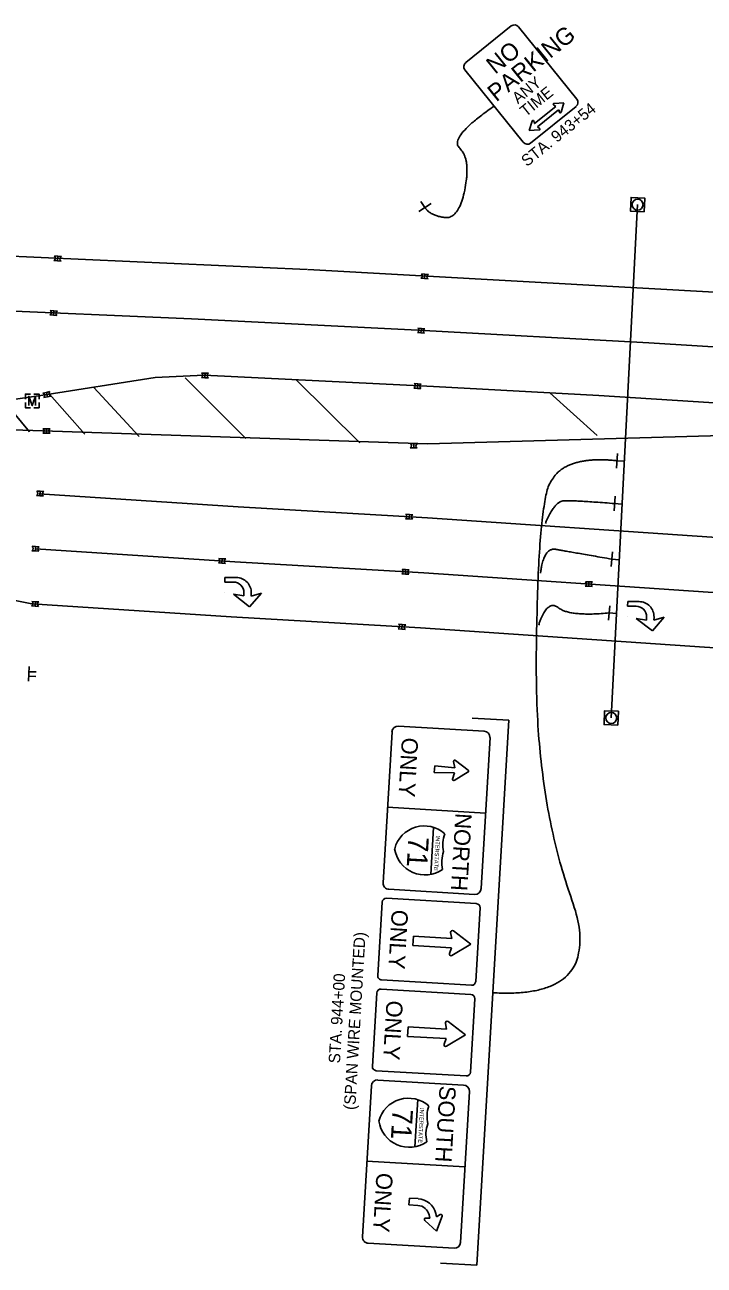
# Model space of a CAD drawing. Extents: x 1847379 to 1850904, y 217032 to 220169.
# Drawn here: x 1848407.3 to 1848555.2, y 218695.2 to 218965.5 of the extents above; entities that cross this region are included whole.
import ezdxf

# ---------------------------------------------------------------- set-up
doc = ezdxf.new("R2010")
doc.units = 0
for name, color, linetype in [('PM_P_Cells', 7, 'Continuous'), ('PM_P_Channelizing_Line', 7, 'Continuous'), ('PM_P_CL_Double_Solid', 7, 'Continuous'), ('PM_P_Edge_Line', 7, 'Continuous'), ('PM_P_Lane_Line', 7, 'Continuous'), ('PM_P_Transverse_Line', 7, 'Continuous'), ('SN_P_Signs', 7, 'Continuous'), ('SN_X_Foundation', 7, 'Continuous'), ('SN_X_Public', 7, 'Continuous'), ('SV_X_Mon_Cells_Found', 7, 'Continuous')]:
    doc.layers.add(name, color=color, linetype=linetype)

msp = doc.modelspace()

# ---------------------------------------------------------------- linework, layer by layer
at = {"layer": 'PM_P_Cells'}
for p, q in [((1848413.6, 218914.14), (1848414.37, 218914.07)), ((1848413.6, 218914.14), (1848414.37, 218914.07)), ((1848414.46, 218915.04), (1848413.69, 218915.11)), ((1848413.69, 218915.11), (1848414.46, 218915.04)), ((1848414.37, 218914.07), (1848414.46, 218915.04)), ((1848414.37, 218914.07), (1848415.14, 218914)), ((1848414.46, 218915.04), (1848415.23, 218914.97)), ((1848493.52, 218910.25), (1848494.28, 218910.18)), ((1848493.52, 218910.25), (1848494.28, 218910.18)), ((1848494.37, 218911.15), (1848493.6, 218911.22)), ((1848493.6, 218911.22), (1848494.37, 218911.15)), ((1848494.28, 218910.18), (1848494.37, 218911.15)), ((1848494.28, 218910.18), (1848495.05, 218910.11)), ((1848494.37, 218911.15), (1848495.14, 218911.08)), ((1848412.73, 218902.28), (1848413.49, 218902.21)), ((1848412.73, 218902.28), (1848413.49, 218902.21)), ((1848413.58, 218903.18), (1848412.81, 218903.25)), ((1848412.81, 218903.25), (1848413.58, 218903.18)), ((1848413.49, 218902.21), (1848413.58, 218903.18)), ((1848413.49, 218902.21), (1848414.26, 218902.14)), ((1848413.58, 218903.18), (1848414.35, 218903.11)), ((1848493.61, 218899.31), (1848492.84, 218899.38)), ((1848492.84, 218899.38), (1848493.61, 218899.31)), ((1848493.52, 218898.34), (1848493.61, 218899.31)), ((1848493.61, 218899.31), (1848494.37, 218899.24)), ((1848492.75, 218898.41), (1848493.52, 218898.34)), ((1848492.75, 218898.41), (1848493.52, 218898.34)), ((1848493.52, 218898.34), (1848494.29, 218898.27)), ((1848446.48, 218888.59), (1848445.71, 218888.6)), ((1848446.5, 218889.57), (1848445.72, 218889.58)), ((1848446.5, 218889.57), (1848446.48, 218888.59)), ((1848446.48, 218888.59), (1848447.25, 218888.58)), ((1848447.25, 218888.58), (1848446.48, 218888.59)), ((1848447.27, 218889.55), (1848446.5, 218889.57)), ((1848447.27, 218889.55), (1848446.5, 218889.57)), ((1848491.97, 218886.34), (1848492.73, 218886.27)), ((1848491.97, 218886.34), (1848492.73, 218886.27)), ((1848492.82, 218887.24), (1848492.05, 218887.31)), ((1848492.05, 218887.31), (1848492.82, 218887.24)), ((1848492.73, 218886.27), (1848492.82, 218887.24)), ((1848492.73, 218886.27), (1848493.5, 218886.2)), ((1848492.82, 218887.24), (1848493.59, 218887.17)), ((1848411.96, 218885.38), (1848411.21, 218885.21)), ((1848412.17, 218884.43), (1848411.42, 218884.26)), ((1848412.71, 218885.55), (1848411.96, 218885.38)), ((1848412.71, 218885.55), (1848411.96, 218885.38)), ((1848411.96, 218885.38), (1848412.17, 218884.43)), ((1848412.17, 218884.43), (1848412.93, 218884.6)), ((1848412.93, 218884.6), (1848412.17, 218884.43)), ((1848411.97, 218877.46), (1848411.2, 218877.46)), ((1848411.2, 218877.46), (1848411.97, 218877.46)), ((1848411.2, 218876.49), (1848411.97, 218876.49)), ((1848411.2, 218876.49), (1848411.97, 218876.49)), ((1848411.97, 218877.46), (1848412.75, 218877.46)), ((1848411.97, 218876.49), (1848411.97, 218877.46)), ((1848411.97, 218876.49), (1848412.75, 218876.49)), ((1848491.16, 218873.29), (1848491.93, 218873.29)), ((1848491.16, 218873.29), (1848491.93, 218873.29)), ((1848491.94, 218874.26), (1848491.17, 218874.27)), ((1848491.17, 218874.27), (1848491.94, 218874.26)), ((1848491.93, 218873.29), (1848491.94, 218874.26)), ((1848491.93, 218873.29), (1848492.7, 218873.28)), ((1848491.94, 218874.26), (1848492.71, 218874.26)), ((1848409.79, 218862.9), (1848410.56, 218862.86)), ((1848409.79, 218862.9), (1848410.56, 218862.86)), ((1848410.62, 218863.83), (1848409.85, 218863.88)), ((1848409.85, 218863.88), (1848410.62, 218863.83)), ((1848410.56, 218862.86), (1848410.62, 218863.83)), ((1848410.56, 218862.86), (1848411.33, 218862.82)), ((1848410.62, 218863.83), (1848411.39, 218863.79)), ((1848490.99, 218858.78), (1848490.22, 218858.84)), ((1848490.22, 218858.84), (1848490.99, 218858.78)), ((1848490.92, 218857.81), (1848490.99, 218858.78)), ((1848490.99, 218858.78), (1848491.76, 218858.73)), ((1848490.15, 218857.86), (1848490.92, 218857.81)), ((1848490.15, 218857.86), (1848490.92, 218857.81)), ((1848490.92, 218857.81), (1848491.69, 218857.75)), ((1848408.79, 218850.87), (1848409.55, 218850.83)), ((1848408.79, 218850.87), (1848409.55, 218850.83)), ((1848409.61, 218851.8), (1848408.84, 218851.85)), ((1848408.84, 218851.85), (1848409.61, 218851.8)), ((1848409.55, 218850.83), (1848409.61, 218851.8)), ((1848409.55, 218850.83), (1848410.32, 218850.79)), ((1848409.61, 218851.8), (1848410.38, 218851.76)), ((1848449.41, 218848.24), (1848450.18, 218848.18)), ((1848449.41, 218848.24), (1848450.18, 218848.18)), ((1848450.26, 218849.15), (1848449.49, 218849.21)), ((1848449.49, 218849.21), (1848450.26, 218849.15)), ((1848450.18, 218848.18), (1848450.26, 218849.15)), ((1848450.18, 218848.18), (1848450.95, 218848.12)), ((1848450.26, 218849.15), (1848451.03, 218849.09)), ((1848489.36, 218845.82), (1848490.13, 218845.8)), ((1848489.36, 218845.82), (1848490.13, 218845.8)), ((1848490.17, 218846.77), (1848489.4, 218846.8)), ((1848489.4, 218846.8), (1848490.17, 218846.77)), ((1848490.13, 218845.8), (1848490.17, 218846.77)), ((1848490.13, 218845.8), (1848490.9, 218845.77)), ((1848490.17, 218846.77), (1848490.94, 218846.74)), ((1848450.82, 218844.07), (1848450.83, 218845.07)), ((1848452.68, 218844.05), (1848450.82, 218844.07)), ((1848450.83, 218845.07), (1848453.31, 218845.05)), ((1848529.27, 218843.16), (1848530.04, 218843.13)), ((1848529.27, 218843.16), (1848530.04, 218843.13)), ((1848530.08, 218844.11), (1848529.31, 218844.14)), ((1848529.31, 218844.14), (1848530.08, 218844.11)), ((1848530.04, 218843.13), (1848530.08, 218844.11)), ((1848530.04, 218843.13), (1848530.81, 218843.1)), ((1848530.08, 218844.11), (1848530.85, 218844.08)), ((1848409.56, 218839.78), (1848408.8, 218839.84)), ((1848408.8, 218839.84), (1848409.56, 218839.78)), ((1848409.49, 218838.81), (1848409.56, 218839.78)), ((1848409.56, 218839.78), (1848410.33, 218839.73)), ((1848450.8, 218841.74), (1848450.8, 218841.74)), ((1848456.21, 218838.69), (1848452.72, 218841.39)), ((1848452.72, 218841.39), (1848454.95, 218841.03)), ((1848454.95, 218841.03), (1848454.96, 218841.73)), ((1848458.8, 218841.66), (1848456.21, 218838.69)), ((1848456.56, 218841.68), (1848456.55, 218841.02)), ((1848456.55, 218841.02), (1848458.8, 218841.66)), ((1848458.8, 218841.66), (1848458.8, 218841.66)), ((1848538.52, 218838.82), (1848538.53, 218839.82)), ((1848538.53, 218839.82), (1848541.01, 218839.8)), ((1848408.72, 218838.86), (1848409.49, 218838.81)), ((1848408.72, 218838.86), (1848409.49, 218838.81)), ((1848409.49, 218838.81), (1848410.26, 218838.75)), ((1848540.38, 218838.8), (1848538.52, 218838.82)), ((1848489.42, 218834.79), (1848488.65, 218834.87)), ((1848488.65, 218834.87), (1848489.42, 218834.79)), ((1848489.32, 218833.82), (1848489.42, 218834.79)), ((1848489.42, 218834.79), (1848490.19, 218834.72)), ((1848538.5, 218836.49), (1848538.5, 218836.49)), ((1848543.91, 218833.44), (1848540.41, 218836.14)), ((1848540.41, 218836.14), (1848542.65, 218835.78)), ((1848542.65, 218835.78), (1848542.66, 218836.49)), ((1848546.5, 218836.41), (1848543.91, 218833.44)), ((1848544.26, 218836.43), (1848544.25, 218835.77)), ((1848544.25, 218835.77), (1848546.5, 218836.41)), ((1848546.5, 218836.41), (1848546.5, 218836.41)), ((1848488.56, 218833.9), (1848489.32, 218833.82)), ((1848488.56, 218833.9), (1848489.32, 218833.82)), ((1848489.32, 218833.82), (1848490.09, 218833.75))]:
    msp.add_line(p, q, dxfattribs=at)
for centre, radius, start, end in [((1848413.34, 218914.65), 0.576, 296.8063, 52.8586), ((1848413.34, 218914.65), 0.576, 296.8063, 52.8586), ((1848415.49, 218914.46), 0.576, 116.8063, 232.8586), ((1848493.26, 218910.76), 0.576, 296.8063, 52.8586), ((1848493.26, 218910.76), 0.576, 296.8063, 52.8586), ((1848495.4, 218910.57), 0.576, 116.8063, 232.8586), ((1848412.47, 218902.79), 0.576, 296.8063, 52.8586), ((1848412.47, 218902.79), 0.576, 296.8063, 52.8586), ((1848414.61, 218902.6), 0.576, 116.8063, 232.8586), ((1848492.49, 218898.92), 0.576, 296.8063, 52.8586), ((1848492.49, 218898.92), 0.576, 296.8063, 52.8586), ((1848494.63, 218898.73), 0.576, 116.8063, 232.8586), ((1848445.41, 218889.09), 0.576, 301.0696, 57.1219), ((1848447.56, 218889.06), 0.576, 121.0696, 237.1219), ((1848447.56, 218889.06), 0.576, 121.0696, 237.1219), ((1848491.71, 218886.85), 0.576, 296.8063, 52.8586), ((1848491.71, 218886.85), 0.576, 296.8063, 52.8586), ((1848493.85, 218886.66), 0.576, 116.8063, 232.8586), ((1848411.02, 218884.67), 0.576, 314.6291, 70.6814), ((1848413.12, 218885.14), 0.576, 134.6291, 250.6814), ((1848413.12, 218885.14), 0.576, 134.6291, 250.6814), ((1848410.9, 218876.98), 0.576, 301.9738, 58.0262), ((1848410.9, 218876.98), 0.576, 301.9738, 58.0262), ((1848413.05, 218876.98), 0.576, 121.9738, 238.0262), ((1848490.86, 218873.79), 0.576, 301.4354, 57.4877), ((1848490.86, 218873.79), 0.576, 301.4354, 57.4877), ((1848493.01, 218873.76), 0.576, 121.4354, 237.4877), ((1848409.51, 218863.41), 0.576, 298.7836, 54.8359), ((1848409.51, 218863.41), 0.576, 298.7836, 54.8359), ((1848411.66, 218863.29), 0.576, 118.7836, 234.8359), ((1848489.88, 218858.37), 0.576, 297.947, 53.9993), ((1848489.88, 218858.37), 0.576, 297.947, 53.9993), ((1848492.02, 218858.22), 0.576, 117.947, 233.9993), ((1848408.51, 218851.38), 0.576, 298.7836, 54.8359), ((1848408.51, 218851.38), 0.576, 298.7836, 54.8359), ((1848410.66, 218851.26), 0.576, 118.7836, 234.8359), ((1848449.15, 218848.75), 0.576, 297.5132, 53.5655), ((1848449.15, 218848.75), 0.576, 297.5132, 53.5655), ((1848451.29, 218848.58), 0.576, 117.5132, 233.5655), ((1848489.08, 218846.32), 0.576, 299.9028, 55.9551), ((1848489.08, 218846.32), 0.576, 299.9028, 55.9551), ((1848491.23, 218846.24), 0.576, 119.9028, 235.9551), ((1848452.66, 218841.76), 2.3, 359.4564, 89.4564), ((1848453.28, 218841.77), 3.28, 358.5479, 89.4564), ((1848528.99, 218843.66), 0.576, 299.9028, 55.9551), ((1848528.99, 218843.66), 0.576, 299.9028, 55.9551), ((1848531.14, 218843.58), 0.576, 119.9028, 235.9551), ((1848408.46, 218839.37), 0.576, 297.7362, 53.7885), ((1848408.46, 218839.37), 0.576, 297.7362, 53.7885), ((1848410.6, 218839.22), 0.576, 117.7362, 233.7885), ((1848540.98, 218836.52), 3.28, 358.5479, 89.4564), ((1848540.36, 218836.51), 2.3, 359.4564, 89.4564), ((1848488.3, 218834.42), 0.576, 296.2627, 52.3151), ((1848488.3, 218834.42), 0.576, 296.2627, 52.3151), ((1848490.44, 218834.2), 0.576, 116.2627, 232.3151)]:
    msp.add_arc(centre, radius, start, end, dxfattribs=at)
at = {"layer": 'PM_P_Channelizing_Line'}
msp.add_lwpolyline([(1848893.84, 218822.16), (1848768.36, 218829.35), (1848699.2, 218833.28), (1848609.68, 218838.48), (1848556.05, 218841.87), (1848494.16, 218846.05), (1848452.97, 218848.49), (1848409.58, 218851.32)], dxfattribs=at)
at = {"layer": 'PM_P_CL_Double_Solid'}
msp.add_line((1848494.98, 218874.17), (1848559.13, 218875.98), dxfattribs=at)
for points in [[(1848092.4, 218893.94), (1848142.1, 218891.52), (1848192.74, 218889.17), (1848244.1, 218886.91), (1848292.7, 218884.63), (1848342.36, 218882.33), (1848384.68, 218880.9), (1848410.72, 218884.71), (1848435.62, 218888.6), (1848446.29, 218889.11), (1848496.28, 218886.67), (1848532.23, 218884.71), (1848581.34, 218881.58), (1848635.08, 218878.63), (1848691.11, 218875.57), (1848742.91, 218872.53), (1848797.97, 218869.41), (1848838.45, 218867.24), (1848839.96, 218866.49), (1848840.79, 218865.04), (1848840.57, 218862.3), (1848839.59, 218860.87), (1848837.82, 218860.26)], [(1848092.21, 218890.95), (1848141.96, 218888.52), (1848192.6, 218886.17), (1848243.96, 218883.92), (1848292.56, 218881.64), (1848342.24, 218879.33), (1848494.98, 218874.17)]]:
    msp.add_lwpolyline(points, dxfattribs=at)
at = {"layer": 'PM_P_Edge_Line'}
for p, q in [((1848468.73, 218912.18), (1848094.69, 218929.11)), ((1848468.87, 218912.17), (1848839.16, 218891.61)), ((1848538.18, 218877.37), (1848538.18, 218877.37)), ((1848324.68, 218855.5), (1848408.8, 218839.34))]:
    msp.add_line(p, q, dxfattribs=at)
msp.add_lwpolyline([(1848816.62, 218814.57), (1848767.67, 218817.37), (1848698.52, 218821.29), (1848608.95, 218826.5), (1848555.27, 218829.89), (1848493.4, 218834.07), (1848452.22, 218836.51), (1848408.8, 218839.34)], dxfattribs=at)
at = {"layer": 'PM_P_Lane_Line'}
for points in [[(1848093.91, 218917.13), (1848143.09, 218915.12), (1848190.28, 218912.91), (1848241.04, 218910.6), (1848292.87, 218908.29), (1848342.88, 218905.97), (1848396.54, 218903.43), (1848443.56, 218901.44), (1848492.82, 218898.95), (1848543.12, 218896.17), (1848588.69, 218893.34), (1848639.37, 218890.51), (1848690.94, 218887.73), (1848738.16, 218885.02), (1848789.62, 218882.19), (1848826.41, 218879.84)], [(1848835.23, 218837.54), (1848769.04, 218841.33), (1848699.89, 218845.26), (1848610.41, 218850.46), (1848556.83, 218853.84), (1848494.92, 218858.02), (1848453.72, 218860.46), (1848410.36, 218863.29)]]:
    msp.add_lwpolyline(points, dxfattribs=at)
at = {"layer": 'PM_P_Transverse_Line'}
for p, q in [((1848422.32, 218886.43), (1848432.16, 218875.78)), ((1848466.33, 218888.13), (1848480.18, 218874.38)), ((1848402.66, 218883.53), (1848408.31, 218876.82)), ((1848420.32, 218876.29), (1848412.64, 218885.01)), ((1848531.88, 218875.96), (1848521.59, 218885.29))]:
    msp.add_line(p, q, dxfattribs=at)
msp.add_lwpolyline([(1848455.38, 218875.37), (1848442.14, 218888.59)], dxfattribs=at)
at = {"layer": 'SN_P_Signs'}
for p, q in [((1848408.04, 218822.45), (1848408.18, 218825.65)), ((1848408.09, 218823.57), (1848409.68, 218823.5)), ((1848408.11, 218824.05), (1848408.11, 218824.05)), ((1848408.11, 218824.05), (1848408.11, 218824.05)), ((1848408.13, 218824.53), (1848409.73, 218824.46))]:
    msp.add_line(p, q, dxfattribs=at)
at = {"layer": 'SN_X_Foundation'}
for points in [[(1848542.11, 218924.73), (1848542.26, 218927.73), (1848539.26, 218927.88), (1848539.11, 218924.88)], [(1848536.4, 218812.9), (1848536.51, 218815.9), (1848533.51, 218816), (1848533.4, 218813.01)]]:
    msp.add_lwpolyline(points, close=True, dxfattribs=at)
for centre in [(1848540.68, 218926.31), (1848534.95, 218814.45)]:
    msp.add_circle(centre, 1.2, dxfattribs=at)
at = {"layer": 'SN_X_Public'}
for p, q in [((1848522.41, 218948.04), (1848522.91, 218947.71)), ((1848524.66, 218948.51), (1848522.5, 218948.37)), ((1848524.06, 218946.44), (1848524.66, 218948.51)), ((1848522.9, 218947.7), (1848518.27, 218943.97)), ((1848520.88, 218945.47), (1848520.88, 218945.47)), ((1848522.91, 218947.71), (1848522.9, 218947.7)), ((1848523.5, 218946.98), (1848523.71, 218946.42)), ((1848517.71, 218944.51), (1848517.11, 218942.44)), ((1848517.11, 218942.44), (1848519.27, 218942.58)), ((1848518.27, 218943.97), (1848518.06, 218944.53)), ((1848518.27, 218943.97), (1848518.28, 218943.98)), ((1848519.36, 218942.91), (1848518.86, 218943.24)), ((1848495.72, 218926.55), (1848493.04, 218924.81)), ((1848494.38, 218925.68), (1848493.51, 218927.02)), ((1848534.95, 218814.45), (1848540.68, 218926.31)), ((1848536.1, 218868.9), (1848536.34, 218872.09)), ((1848536.22, 218870.5), (1848537.82, 218870.38)), ((1848535.56, 218859.57), (1848535.8, 218862.76)), ((1848535.68, 218861.16), (1848537.28, 218861.04)), ((1848534.96, 218847.46), (1848535.2, 218850.65)), ((1848535.08, 218849.05), (1848536.68, 218848.93)), ((1848534.38, 218835.72), (1848534.62, 218838.91)), ((1848534.5, 218837.32), (1848536.09, 218837.2)), ((1848504.69, 218814.39), (1848512.62, 218813.93)), ((1848512.62, 218813.93), (1848505.7, 218695.2)), ((1848500.86, 218803.59), (1848500.63, 218804.98)), ((1848501.01, 218805.21), (1848503.78, 218803.05)), ((1848496.42, 218802.55), (1848496.5, 218804.03)), ((1848500.8, 218802.48), (1848496.42, 218802.55)), ((1848496.5, 218804.03), (1848500.86, 218803.59)), ((1848500.4, 218801.13), (1848500.8, 218802.48)), ((1848500.42, 218803.06), (1848500.42, 218803.06)), ((1848503.76, 218802.67), (1848500.76, 218800.85)), ((1848507.58, 218793.71), (1848486.24, 218794.97)), ((1848496.26, 218790.61), (1848495.66, 218780.34)), ((1848493.13, 218785.64), (1848493.13, 218785.64)), ((1848491.77, 218764.83), (1848491.89, 218766.91)), ((1848491.89, 218766.91), (1848500.26, 218766.42)), ((1848500.26, 218766.42), (1848499.98, 218767.67)), ((1848500.57, 218768.04), (1848504.35, 218765.14)), ((1848500.14, 218764.34), (1848491.77, 218764.83)), ((1848499.71, 218763.13), (1848500.14, 218764.34)), ((1848504.35, 218765.14), (1848500.25, 218762.69)), ((1848499.11, 218746.64), (1848498.83, 218747.89)), ((1848499.42, 218748.27), (1848503.2, 218745.36)), ((1848490.62, 218745.06), (1848490.74, 218747.13)), ((1848490.74, 218747.13), (1848499.11, 218746.64)), ((1848503.2, 218745.36), (1848499.1, 218742.91)), ((1848498.99, 218744.56), (1848490.62, 218745.06)), ((1848498.56, 218743.35), (1848498.99, 218744.56)), ((1848492.82, 218731.27), (1848492.21, 218721.01)), ((1848489.68, 218726.31), (1848489.68, 218726.31)), ((1848503.09, 218716.6), (1848481.75, 218717.85)), ((1848490.9, 218708.33), (1848490.99, 218709.81)), ((1848492.83, 218708.22), (1848490.9, 218708.33)), ((1848490.99, 218709.81), (1848492.91, 218709.7)), ((1848494.89, 218708.16), (1848494.89, 218708.16)), ((1848494.89, 218708.16), (1848494.89, 218708.16)), ((1848496.9, 218702.64), (1848494.34, 218704.95)), ((1848494.56, 218705.47), (1848495.48, 218705.41)), ((1848495.48, 218705.41), (1848495.3, 218706.14)), ((1848496.75, 218706.48), (1848496.92, 218705.75)), ((1848498.14, 218705.86), (1848496.9, 218702.64)), ((1848496.92, 218705.75), (1848497.71, 218706.22)), ((1848497.78, 218695.66), (1848505.7, 218695.2))]:
    msp.add_line(p, q, dxfattribs=at)
for points in [[(1848513.18, 218965.24), (1848503.25, 218957.24)], [(1848527.47, 218949.3), (1848514.76, 218965.07)], [(1848503.08, 218955.66), (1848515.79, 218939.89)], [(1848517.37, 218939.72), (1848527.3, 218947.72)], [(1848518.86, 218943.24), (1848523.49, 218946.97)], [(1848487.21, 218811.42), (1848485.27, 218778.52)], [(1848507.29, 218811.57), (1848488.62, 218812.67)], [(1848506.61, 218777.27), (1848508.55, 218810.16)], [(1848505.54, 218773.99), (1848485.98, 218775.14)], [(1848486.53, 218777.11), (1848505.2, 218776.01)], [(1848485.04, 218774.3), (1848484.1, 218758.3)], [(1848505.44, 218757.04), (1848506.38, 218773.05)], [(1848484.94, 218757.36), (1848504.5, 218756.21)], [(1848483.89, 218754.52), (1848482.95, 218738.52)], [(1848504.39, 218754.21), (1848484.83, 218755.36)], [(1848504.29, 218737.26), (1848505.23, 218753.27)], [(1848483.79, 218737.58), (1848503.35, 218736.43)], [(1848502.8, 218734.46), (1848484.13, 218735.55)], [(1848482.72, 218734.3), (1848480.78, 218701.4)], [(1848502.12, 218700.15), (1848504.05, 218733.04)], [(1848482.04, 218699.99), (1848500.71, 218698.89)]]:
    msp.add_lwpolyline(points, dxfattribs=at)
for centre, radius, start, end in [((1848513.89, 218964.36), 1.12, 38.8676, 128.8676), ((1848503.96, 218956.36), 1.12, 128.8676, 218.8676), ((1848522.51, 218948.19), 0.182, 93.7884, 236.5054), ((1848526.59, 218948.6), 1.12, 308.8676, 38.8676), ((1848523.88, 218946.49), 0.182, 201.2298, 343.9469), ((1848517.89, 218944.46), 0.182, 21.2298, 163.9469), ((1848519.26, 218942.76), 0.182, 273.7884, 56.5054), ((1848516.67, 218940.59), 1.12, 218.8676, 308.8676), ((1848488.54, 218811.34), 1.34, 86.6344, 176.6344), ((1848507.21, 218810.24), 1.34, 356.6344, 86.6344), ((1848500.87, 218805.02), 0.24, 52.1373, 189.6107), ((1848503.63, 218802.87), 0.24, 302.5408, 50.7281), ((1848500.63, 218801.06), 0.24, 163.6582, 301.1316), ((1848494.25, 218784.24), 6.68, 48.3034, 165.0975), ((1848504.95, 218786.9), 6.68, 159.6435, 193.6254), ((1848494.4, 218786.91), 6.68, 188.1714, 304.9655), ((1848504.72, 218783.01), 6.68, 159.6435, 193.6254), ((1848486.61, 218778.44), 1.34, 176.6344, 266.6344), ((1848485.93, 218774.25), 0.891, 86.6344, 176.6344), ((1848505.28, 218777.34), 1.34, 266.6344, 356.6344), ((1848505.49, 218773.1), 0.891, 356.6344, 86.6344), ((1848500.34, 218767.75), 0.371, 52.4434, 192.6788), ((1848500.06, 218763.01), 0.371, 160.5901, 300.8255), ((1848484.99, 218758.24), 0.891, 176.6344, 266.6344), ((1848504.55, 218757.09), 0.891, 266.6344, 356.6344), ((1848484.78, 218754.47), 0.891, 86.6344, 176.6344), ((1848504.34, 218753.32), 0.891, 356.6344, 86.6344), ((1848499.19, 218747.97), 0.371, 52.4434, 192.6788), ((1848498.91, 218743.23), 0.371, 160.5901, 300.8255), ((1848483.84, 218738.47), 0.891, 176.6344, 266.6344), ((1848503.4, 218737.32), 0.891, 266.6344, 356.6344), ((1848484.05, 218734.22), 1.34, 86.6344, 176.6344), ((1848502.72, 218733.12), 1.34, 356.6344, 86.6344), ((1848490.8, 218724.9), 6.68, 48.3034, 165.0975), ((1848501.51, 218727.56), 6.68, 159.6435, 193.6254), ((1848490.96, 218727.57), 6.68, 188.1714, 304.9655), ((1848501.28, 218723.67), 6.68, 159.6435, 193.6254), ((1848492.67, 218705.51), 2.71, 13.3612, 86.6344), ((1848492.67, 218705.51), 4.19, 13.3612, 86.6344), ((1848494.54, 218705.17), 0.297, 85.9994, 227.8775), ((1848497.86, 218705.96), 0.297, 338.845, 120.7231), ((1848482.12, 218701.32), 1.34, 176.6344, 266.6344), ((1848500.79, 218700.23), 1.34, 266.6344, 356.6344)]:
    msp.add_arc(centre, radius, start, end, dxfattribs=at)
for points in [[(1848494.38, 218925.68), (1848495.52, 218923.92), (1848501.77, 218923.07), (1848504.39, 218936.26), (1848499.49, 218940.91), (1848509.44, 218947.77)], [(1848536.22, 218870.5), (1848523.26, 218871.87), (1848518.85, 218856.51), (1848518.41, 218797.23), (1848534.12, 218753.09), (1848509.16, 218754.56)], [(1848535.68, 218861.16), (1848526.56, 218861.89), (1848522.57, 218861.63), (1848520.6, 218856.81)], [(1848535.08, 218849.05), (1848525.61, 218850.69), (1848520.25, 218851.69), (1848519.55, 218846.01)], [(1848534.5, 218837.32), (1848525.85, 218836.52), (1848521.04, 218840.39), (1848519.15, 218834.7)]]:
    msp.add_open_spline(points, degree=2, dxfattribs=at)
at = {"layer": 'SV_X_Mon_Cells_Found'}
msp.add_line((1848408.87, 218883.53), (1848408.87, 218883.53), dxfattribs=at)
for points in [[(1848407.37, 218883.91), (1848407.37, 218885.03), (1848408.49, 218885.03)], [(1848408.49, 218882.03), (1848407.37, 218882.03), (1848407.37, 218883.15)], [(1848408.13, 218882.53), (1848408.13, 218884.53), (1848408.87, 218882.53), (1848409.61, 218884.53), (1848409.61, 218882.53)], [(1848409.22, 218885.03), (1848410.37, 218885.03), (1848410.37, 218883.91)], [(1848410.37, 218883.15), (1848410.37, 218882.03), (1848409.22, 218882.03)]]:
    msp.add_lwpolyline(points, dxfattribs=at)

# ---------------------------------------------------------------- texts
at = {"layer": 'SN_X_Public'}
for s, height, rotation, p in [('PARKING', 3.75, 38.8676, (1848509.92, 218948.56)), ('NO', 3.75, 38.8676, (1848509.66, 218954.58)), ('ANY', 2.5, 38.8676, (1848514.63, 218948.15)), ('TIME', 2.5, 38.8676, (1848516.34, 218945.31)), ('STA. 943+54', 2.5, 38.8676, (1848516.59, 218934.47)), ('ONLY', 3.562, 266.6344, (1848489.37, 218810.25)), ('NORTH', 3.562, 266.6344, (1848501.04, 218793.78)), ('INTERSTATE', 0.891, 266.6344, (1848496.77, 218788.81)), ('71', 4.453, 266.6344, (1848490.8, 218788.67)), ('ONLY', 3.562, 266.6344, (1848487.18, 218772.73)), ('(SPAN WIRE MOUNTED)', 2.5, 86.6344, (1848479.2, 218728.98)), ('STA. 944+00', 2.5, 86.6344, (1848475.88, 218739.12)), ('ONLY', 3.562, 266.6344, (1848486.03, 218752.95)), ('SOUTH', 3.562, 266.6344, (1848497.59, 218734.37)), ('INTERSTATE', 0.891, 266.6344, (1848493.32, 218729.47)), ('71', 4.453, 266.6344, (1848487.35, 218729.33)), ('ONLY', 3.562, 266.6344, (1848483.84, 218715.39))]:
    msp.add_text(s, height=height, rotation=rotation, dxfattribs=at).set_placement(p)

doc.saveas('drawing.dxf')
